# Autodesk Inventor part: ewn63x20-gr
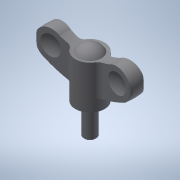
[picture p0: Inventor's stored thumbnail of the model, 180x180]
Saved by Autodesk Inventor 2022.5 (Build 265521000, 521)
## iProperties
Created: 2017-05
Part Number: ewn63x20-gr
Material: 一般
Document SubType Name: Modeling
Designer: imaocorp
Density: 1 g/cm^3
Appearance: 既定
Author: imaocorp
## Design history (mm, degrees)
node "ewn63x20-gr.x_t1"
node "ewn63x20-gr"
node "Base1"
